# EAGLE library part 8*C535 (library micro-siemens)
80C515/80C535 8-Bit CMOS Single-Chip Microcontroller Source: http://www.infineon.com/cmc_upload/migrated_files/document_files/Datasheet/d80515.pdf This device has been discontinued !!!
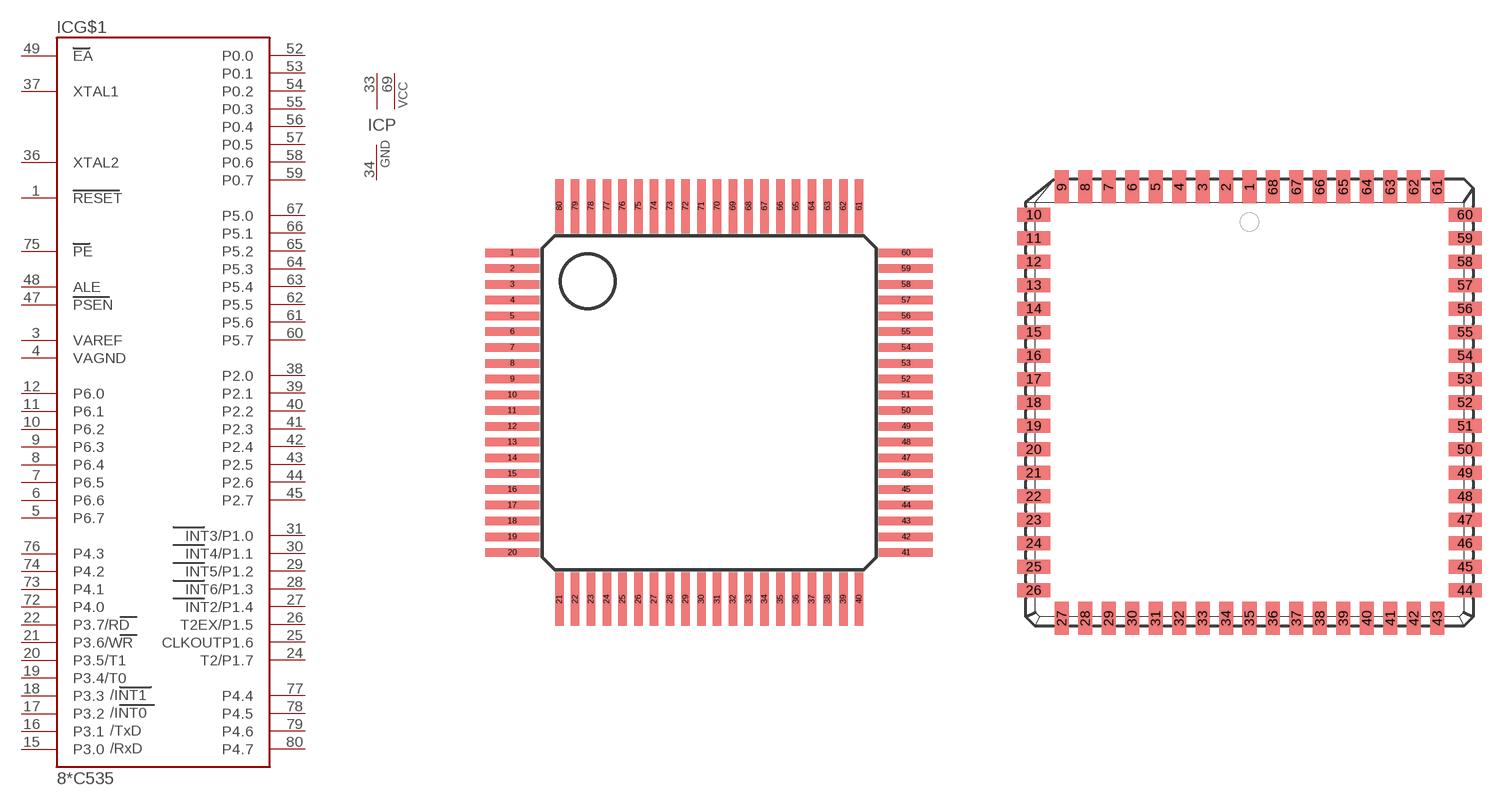
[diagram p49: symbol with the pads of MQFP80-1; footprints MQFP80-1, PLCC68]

Designator prefix IC; gates G$1=80C535-1 P=2VCC1GND

## 80C535M (OC_FARNELL: unknown; OC_NEWARK: unknown), 83C535M (OC_FARNELL: unknown; OC_NEWARK: unknown), 87C535M (OC_FARNELL: unknown; OC_NEWARK: unknown)  [MQFP80-1]
1  G$1:RESET  in
3  G$1:VAREF
4  G$1:VAGND
5  G$1:P6.7  in
6  G$1:P6.6  in
7  G$1:P6.5  in
8  G$1:P6.4  in
9  G$1:P6.3  in
10  G$1:P6.2  in
11  G$1:P6.1  in
12  G$1:P6.0  in
15  G$1:P3.0
16  G$1:P3.1
17  G$1:P3.2
18  G$1:P3.3
19  G$1:P3.4/T0
20  G$1:P3.5/T1
21  G$1:P3.6/WR
22  G$1:P3.7/RD
24  G$1:T2/P1.7
25  G$1:CLKOUTP1.6
26  G$1:T2EX/P1.5
27  G$1:INT2/P1.4
28  G$1:INT6/P1.3
29  G$1:INT5/P1.2
30  G$1:INT4/P1.1
31  G$1:INT3/P1.0
33  P:VCC  pwr
34  P:GND  pwr
36  G$1:XTAL2  in
37  G$1:XTAL1  in
38  G$1:P2.0
39  G$1:P2.1
40  G$1:P2.2
41  G$1:P2.3
42  G$1:P2.4
43  G$1:P2.5
44  G$1:P2.6
45  G$1:P2.7
47  G$1:PSEN  out
48  G$1:ALE  out
49  G$1:EA  in
52  G$1:P0.0
53  G$1:P0.1
54  G$1:P0.2
55  G$1:P0.3
56  G$1:P0.4
57  G$1:P0.5
58  G$1:P0.6
59  G$1:P0.7
60  G$1:P5.7
61  G$1:P5.6
62  G$1:P5.5
63  G$1:P5.4
64  G$1:P5.3
65  G$1:P5.2
66  G$1:P5.1
67  G$1:P5.0
69  P:VCC  pwr
72  G$1:P4.0
73  G$1:P4.1
74  G$1:P4.2
75  G$1:PE  in
76  G$1:P4.3
77  G$1:P4.4
78  G$1:P4.5
79  G$1:P4.6
80  G$1:P4.7

## 8C535N (OC_FARNELL: unknown; OC_NEWARK: unknown)  [PLCC68]
1  G$1:P4.0
2  G$1:P4.1
3  G$1:P4.2
4  G$1:PE  in
5  G$1:P4.3
6  G$1:P4.4
7  G$1:P4.5
8  G$1:P4.6
9  G$1:P4.7
10  G$1:RESET  in
11  G$1:VAREF
12  G$1:VAGND
13  G$1:P6.7  in
14  G$1:P6.6  in
15  G$1:P6.5  in
16  G$1:P6.4  in
17  G$1:P6.3  in
18  G$1:P6.2  in
19  G$1:P6.1  in
20  G$1:P6.0  in
21  G$1:P3.0
22  G$1:P3.1
23  G$1:P3.2
24  G$1:P3.3
25  G$1:P3.4/T0
26  G$1:P3.5/T1
27  G$1:P3.6/WR
28  G$1:P3.7/RD
29  G$1:T2/P1.7
30  G$1:CLKOUTP1.6
31  G$1:T2EX/P1.5
32  G$1:INT2/P1.4
33  G$1:INT6/P1.3
34  G$1:INT5/P1.2
35  G$1:INT4/P1.1
36  G$1:INT3/P1.0
37  P:VCC  pwr
38  P:GND  pwr
39  G$1:XTAL2  in
40  G$1:XTAL1  in
41  G$1:P2.0
42  G$1:P2.1
43  G$1:P2.2
44  G$1:P2.3
45  G$1:P2.4
46  G$1:P2.5
47  G$1:P2.6
48  G$1:P2.7
49  G$1:PSEN  out
50  G$1:ALE  out
51  G$1:EA  in
52  G$1:P0.0
53  G$1:P0.1
54  G$1:P0.2
55  G$1:P0.3
56  G$1:P0.4
57  G$1:P0.5
58  G$1:P0.6
59  G$1:P0.7
60  G$1:P5.7
61  G$1:P5.6
62  G$1:P5.5
63  G$1:P5.4
64  G$1:P5.3
65  G$1:P5.2
66  G$1:P5.1
67  G$1:P5.0
68  P:VCC  pwr

## 8C535N-S (OC_FARNELL: unknown; OC_NEWARK: unknown)  [PLCC68SOCK]
Pads as for PLCC68

## Footprint MQFP80-1 (pad centres in mm)
Metric Quad Flat Pack
smd 2.2 x 0.35: 1 -8.125,6.175; 2 -8.125,5.525; 3 -8.125,4.875; 4 -8.125,4.225; 5 -8.125,3.575; 6 -8.125,2.925; 7 -8.125,2.275; 8 -8.125,1.625; 9 -8.125,0.975; 10 -8.125,0.325; 11 -8.125,-0.325; 12 -8.125,-0.975; 13 -8.125,-1.625; 14 -8.125,-2.275; 15 -8.125,-2.925; 16 -8.125,-3.575; 17 -8.125,-4.225; 18 -8.125,-4.875; 19 -8.125,-5.525; 20 -8.125,-6.175; 41 8.1,-6.175; 42 8.1,-5.525; 43 8.1,-4.875; 44 8.1,-4.225; 45 8.1,-3.575; 46 8.1,-2.925; 47 8.1,-2.275; 48 8.1,-1.625; 49 8.1,-0.975; 50 8.1,-0.325; 51 8.1,0.325; 52 8.1,0.975; 53 8.1,1.625; 54 8.1,2.275; 55 8.1,2.925; 56 8.1,3.575; 57 8.1,4.225; 58 8.1,4.875; 59 8.1,5.525; 60 8.1,6.175
smd 0.35 x 2.2: 21 -6.175,-8.1; 22 -5.525,-8.1; 23 -4.875,-8.1; 24 -4.225,-8.1; 25 -3.575,-8.1; 26 -2.925,-8.1; 27 -2.275,-8.1; 28 -1.625,-8.1; 29 -0.975,-8.1; 30 -0.325,-8.1; 31 0.325,-8.1; 32 0.975,-8.1; 33 1.625,-8.1; 34 2.275,-8.1; 35 2.925,-8.1; 36 3.575,-8.1; 37 4.225,-8.1; 38 4.875,-8.1; 39 5.525,-8.1; 40 6.175,-8.1; 61 6.175,8.1; 62 5.525,8.1; 63 4.875,8.1; 64 4.225,8.1; 65 3.575,8.1; 66 2.925,8.1; 67 2.275,8.1; 68 1.625,8.1; 69 0.975,8.1; 70 0.325,8.1; 71 -0.325,8.1; 72 -0.975,8.1; 73 -1.625,8.1; 74 -2.275,8.1; 75 -2.925,8.1; 76 -3.575,8.1; 77 -4.225,8.1; 78 -4.875,8.1; 79 -5.525,8.1; 80 -6.175,8.1

## Footprint PLCC68 (pad centres in mm)
PLASTIC LEADED CHIP CARRIER square
smd 0.76 x 1.8: 1 0,11.67; 2 -1.27,11.67; 3 -2.54,11.67; 4 -3.81,11.67; 5 -5.08,11.67; 6 -6.35,11.67; 7 -7.62,11.67; 8 -8.89,11.67; 9 -10.16,11.67; 27 -10.16,-11.67; 28 -8.89,-11.67; 29 -7.62,-11.67; 30 -6.35,-11.67; 31 -5.08,-11.67; 32 -3.81,-11.67; 33 -2.54,-11.67; 34 -1.27,-11.67; 35 0,-11.67; 36 1.27,-11.67; 37 2.54,-11.67; 38 3.81,-11.67; 39 5.08,-11.67; 40 6.35,-11.67; 41 7.62,-11.67; 42 8.89,-11.67; 43 10.16,-11.67; 61 10.16,11.67; 62 8.89,11.67; 63 7.62,11.67; 64 6.35,11.67; 65 5.08,11.67; 66 3.81,11.67; 67 2.54,11.67; 68 1.27,11.67
smd 1.8 x 0.76: 10 -11.67,10.16; 11 -11.67,8.89; 12 -11.67,7.62; 13 -11.67,6.35; 14 -11.67,5.08; 15 -11.67,3.81; 16 -11.67,2.54; 17 -11.67,1.27; 18 -11.67,0; 19 -11.67,-1.27; 20 -11.67,-2.54; 21 -11.67,-3.81; 22 -11.67,-5.08; 23 -11.67,-6.35; 24 -11.67,-7.62; 25 -11.67,-8.89; 26 -11.67,-10.16; 44 11.67,-10.16; 45 11.67,-8.89; 46 11.67,-7.62; 47 11.67,-6.35; 48 11.67,-5.08; 49 11.67,-3.81; 50 11.67,-2.54; 51 11.67,-1.27; 52 11.67,0; 53 11.67,1.27; 54 11.67,2.54; 55 11.67,3.81; 56 11.67,5.08; 57 11.67,6.35; 58 11.67,7.62; 59 11.67,8.89; 60 11.67,10.16

## Footprint PLCC68SOCK (pad centres in mm)
PLASTIC LEADED CHIP CARRIER socked
drill 0.813 round: 1 0,12.7
drill 0.813 octagon: 2 0,10.16; 3 -2.54,12.7; 4 -2.54,10.16; 5 -5.08,12.7; 6 -5.08,10.16; 7 -7.62,12.7; 8 -7.62,10.16; 9 -10.16,12.7; 10 -12.7,10.16; 11 -10.16,10.16; 12 -12.7,7.62; 13 -10.16,7.62; 14 -12.7,5.08; 15 -10.16,5.08; 16 -12.7,2.54; 17 -10.16,2.54; 18 -12.7,0; 19 -10.16,0; 20 -12.7,-2.54; 21 -10.16,-2.54; 22 -12.7,-5.08; 23 -10.16,-5.08; 24 -12.7,-7.62; 25 -10.16,-7.62; 26 -12.7,-10.16; 27 -10.16,-12.7; 28 -10.16,-10.16; 29 -7.62,-12.7; 30 -7.62,-10.16; 31 -5.08,-12.7; 32 -5.08,-10.16; 33 -2.54,-12.7; 34 -2.54,-10.16; 35 0,-12.7; 36 0,-10.16; 37 2.54,-12.7; 38 2.54,-10.16; 39 5.08,-12.7; 40 5.08,-10.16; 41 7.62,-12.7; 42 7.62,-10.16; 43 10.16,-12.7; 44 12.7,-10.16; 45 10.16,-10.16; 46 12.7,-7.62; 47 10.16,-7.62; 48 12.7,-5.08; 49 10.16,-5.08; 50 12.7,-2.54; 51 10.16,-2.54; 52 12.7,0; 53 10.16,0; 54 12.7,2.54; 55 10.16,2.54; 56 12.7,5.08; 57 10.16,5.08; 58 12.7,7.62; 59 10.16,7.62; 60 12.7,10.16; 61 10.16,12.7; 62 10.16,10.16; 63 7.62,12.7; 64 7.62,10.16; 65 5.08,12.7; 66 5.08,10.16; 67 2.54,12.7; 68 2.54,10.16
